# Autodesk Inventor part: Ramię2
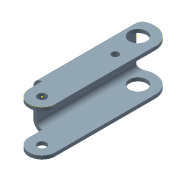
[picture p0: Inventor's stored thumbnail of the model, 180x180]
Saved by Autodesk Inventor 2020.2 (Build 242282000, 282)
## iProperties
Created: 2005-10
Part Number: Ramię2
Document SubType Name: Modeling
Designer: F.Stasiak
Density: 1 g/cm^3
Material: Ogólny
Appearance: Niebieski pastelowy
Manager: www.cadconsulting.pl
Company: Fabian Stasiak CAD Consulting
Author: F.Stasiak
Subject: Zbiór ćwiczeń. Autodesk Inventor 2020. Kurs podstawowy
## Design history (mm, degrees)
sketch "Szkic1"
  geometry: L1 (-395.199, -54.254)-(-195.199, -54.254); L2 (-195.199, -54.254)-(-195.199, -654.254); L3 (-195.199, -654.254)-(-395.199, -654.254); L4 (-395.199, -654.254)-(-395.199, -54.254)
  constraints: 8 end point, 2 parallel, 1 horizontal, 1 perpendicular
  dimensions: "d0" = 600 distance of L3.end L1.start; "d1" = 200 distance of L2.end L3.end
extrude "Wyciągnięcie proste1" new body sketch "Szkic1" distance "d2" = 260; taper "d3" = 0 deg
fillet "Zaokrąglenie1" dims "d5" = 50, "d6" = 100
feature "Skorupa2" dims "d7" = 20
sketch "Szkic2"
  geometry: L1 (0, 240)-(150, 240) reference; L2 (150, 260)-(0, 260) reference; L3 (150, 240)-(150, 260) reference; L4 (150, 20)-(0, 20) reference; L5 (150, 0)-(0, 0) reference; L6 (150, 0)-(150, 20) reference; L7 (0, 0)-(0, 20); L8 (0, 240)-(0, 260)
  constraints: 4 end point, 2 equal length
extrude "Wyciągnięcie proste2" join sketch "Szkic2" distance "d8" = 150; taper "d9" = 0 deg
fillet "Zaokrąglenie2" dims "d10" = 75
sketch "Szkic3"
  geometry: A1 r 100 centre (-295.199, -154.254) between (-195.199, -154.254) and (-295.199, -54.254) reference; A2 r 75 centre (-270.199, -729.254) between (-345.199, -729.254) and (-195.199, -729.254) reference
hole "Otwór1" sketch "Szkic3" diameter "d11" = 100; stored, may be unused: countersink angle "d15" = 90 deg, drill point angle "d17" = 118 deg; dims "d12" = 6, "d13" = 4, "d14" = 2, "d16" = 8
hole "Otwór2" sketch "Szkic3" diameter "d18" = 50; stored, may be unused: countersink angle "d22" = 90 deg, drill point angle "d24" = 118 deg; dims "d19" = 6, "d20" = 4, "d21" = 2, "d23" = 8
chamfer "Faza1" distance "d25" = 50; stored, may be unused: second distance "d26" = 2, angle "d27" = 45 deg
fillet "Zaokrąglenie3" dims "d28" = 100
sketch "Szkic5"
  geometry: L1 (-270.199, -729.254)-(-270.199, -309.254); C1 r 25 at (-270.199, -729.254) reference; C2 r 20 at (-270.199, -309.254)
  constraints: 2 end point, 1 centre point, 1 coincident, 1 vertical
  dimensions: "d33" = 420 distance of L1.start L1.end; "d34" = 40 diameter of C2
extrude "Wyciągnięcie proste4" cut sketch "Szkic5" stored distance "d35" = 10; taper "d36" = 0 deg
node "Bryła1"
node "Korpusy bryłowe"
node "Korpusy powierzchniowe"
